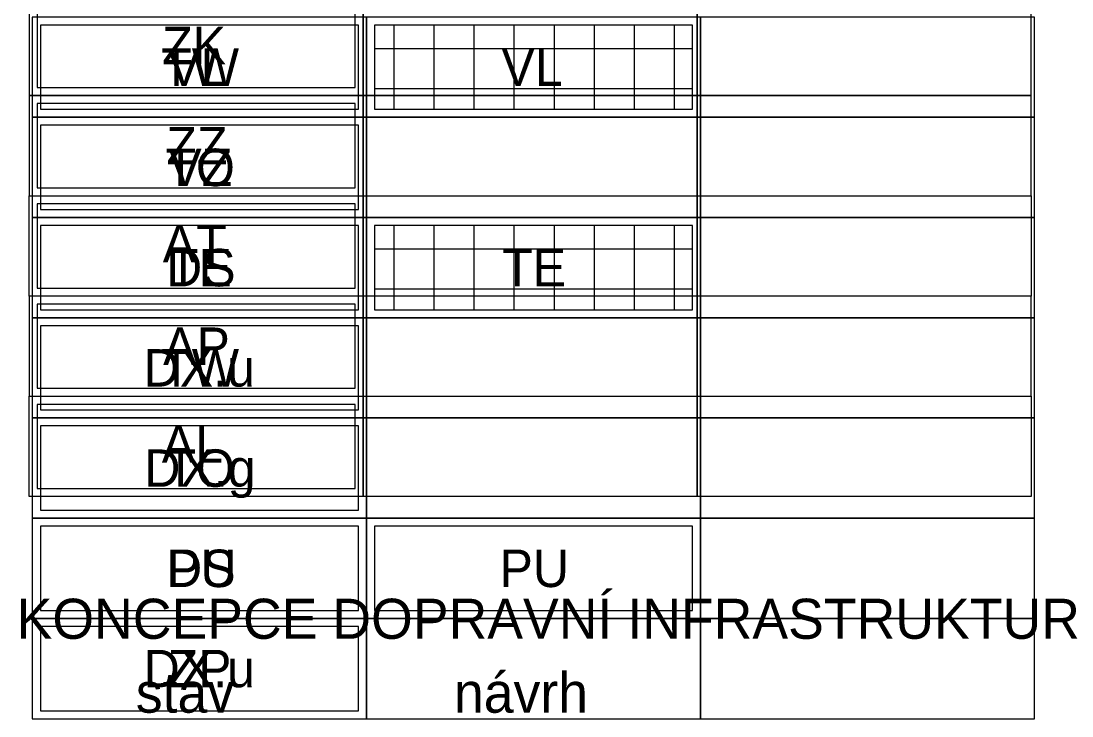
# Model space of a CAD drawing. Extents: x -557692 to -550384, y -1187532 to -1181973.
# Drawn here: x -552824 to -552430.7, y -1183626.2 to -1183366.2 of the extents above; entities that cross this region are included whole.
import ezdxf

# ---------------------------------------------------------------- set-up
doc = ezdxf.new("R2010")
doc.units = 0
for name, color, linetype in [('LEG_2a', 7, 'Continuous'), ('LEG_2b', 7, 'Continuous'), ('LEG_4_KOO', 7, 'Continuous')]:
    doc.layers.add(name, color=color, linetype=linetype)

msp = doc.modelspace()

# ---------------------------------------------------------------- linework, layer by layer
at = {"layer": 'LEG_2a'}
for points in [[(-552820.95, -1183394.08), (-552695.95, -1183394.08), (-552695.95, -1183356.58), (-552820.95, -1183356.58)], [(-552695.95, -1183394.08), (-552570.95, -1183394.08), (-552570.95, -1183356.58), (-552695.95, -1183356.58)], [(-552570.95, -1183394.08), (-552445.95, -1183394.08), (-552445.95, -1183356.58), (-552570.95, -1183356.58)], [(-552817.95, -1183391.08), (-552698.95, -1183391.08), (-552698.95, -1183359.58), (-552817.95, -1183359.58)], [(-552817.95, -1183391.08), (-552698.95, -1183391.08), (-552698.95, -1183359.58), (-552817.95, -1183359.58)], [(-552820.95, -1183431.58), (-552695.95, -1183431.58), (-552695.95, -1183394.08), (-552820.95, -1183394.08)], [(-552817.95, -1183428.58), (-552698.95, -1183428.58), (-552698.95, -1183397.08), (-552817.95, -1183397.08)], [(-552817.95, -1183428.58), (-552698.95, -1183428.58), (-552698.95, -1183397.08), (-552817.95, -1183397.08)], [(-552695.95, -1183431.58), (-552570.95, -1183431.58), (-552570.95, -1183394.08), (-552695.95, -1183394.08)], [(-552570.95, -1183431.58), (-552445.95, -1183431.58), (-552445.95, -1183394.08), (-552570.95, -1183394.08)], [(-552820.95, -1183431.58), (-552695.95, -1183431.58), (-552695.95, -1183469.08), (-552820.95, -1183469.08)], [(-552820.95, -1183431.58), (-552695.95, -1183431.58), (-552695.95, -1183469.08), (-552820.95, -1183469.08)], [(-552695.95, -1183431.58), (-552570.95, -1183431.58), (-552570.95, -1183469.08), (-552695.95, -1183469.08)], [(-552570.95, -1183431.58), (-552445.95, -1183431.58), (-552445.95, -1183469.08), (-552570.95, -1183469.08)], [(-552817.95, -1183466.08), (-552698.95, -1183466.08), (-552698.95, -1183434.58), (-552817.95, -1183434.58)], [(-552817.95, -1183466.08), (-552698.95, -1183466.08), (-552698.95, -1183434.58), (-552817.95, -1183434.58)], [(-552820.95, -1183506.58), (-552695.95, -1183506.58), (-552695.95, -1183469.08), (-552820.95, -1183469.08)], [(-552817.95, -1183503.58), (-552698.95, -1183503.58), (-552698.95, -1183472.08), (-552817.95, -1183472.08)], [(-552817.95, -1183503.58), (-552698.95, -1183503.58), (-552698.95, -1183472.08), (-552817.95, -1183472.08)], [(-552695.95, -1183506.58), (-552570.95, -1183506.58), (-552570.95, -1183469.08), (-552695.95, -1183469.08)], [(-552570.95, -1183506.58), (-552445.95, -1183506.58), (-552445.95, -1183469.08), (-552570.95, -1183469.08)], [(-552820.95, -1183506.58), (-552695.95, -1183506.58), (-552695.95, -1183544.08), (-552820.95, -1183544.08)], [(-552820.95, -1183506.58), (-552695.95, -1183506.58), (-552695.95, -1183544.08), (-552820.95, -1183544.08)], [(-552695.95, -1183506.58), (-552570.95, -1183506.58), (-552570.95, -1183544.08), (-552695.95, -1183544.08)], [(-552570.95, -1183506.58), (-552445.95, -1183506.58), (-552445.95, -1183544.08), (-552570.95, -1183544.08)], [(-552817.95, -1183541.08), (-552698.95, -1183541.08), (-552698.95, -1183509.58), (-552817.95, -1183509.58)], [(-552817.95, -1183541.08), (-552698.95, -1183541.08), (-552698.95, -1183509.58), (-552817.95, -1183509.58)]]:
    msp.add_lwpolyline(points, close=True, dxfattribs=at)
at = {"layer": 'LEG_2b'}
for points in [[(-552819.73, -1183402.18), (-552694.73, -1183402.18), (-552694.73, -1183364.68), (-552819.73, -1183364.68)], [(-552694.73, -1183402.18), (-552569.73, -1183402.18), (-552569.73, -1183364.68), (-552694.73, -1183364.68)], [(-552569.73, -1183402.18), (-552444.73, -1183402.18), (-552444.73, -1183364.68), (-552569.73, -1183364.68)], [(-552816.73, -1183399.18), (-552697.73, -1183399.18), (-552697.73, -1183367.68), (-552816.73, -1183367.68)], [(-552816.73, -1183399.18), (-552697.73, -1183399.18), (-552697.73, -1183367.68), (-552816.73, -1183367.68)], [(-552819.73, -1183439.68), (-552694.73, -1183439.68), (-552694.73, -1183402.18), (-552819.73, -1183402.18)], [(-552816.73, -1183436.68), (-552697.73, -1183436.68), (-552697.73, -1183405.18), (-552816.73, -1183405.18)], [(-552816.73, -1183436.68), (-552697.73, -1183436.68), (-552697.73, -1183405.18), (-552816.73, -1183405.18)], [(-552694.73, -1183439.68), (-552569.73, -1183439.68), (-552569.73, -1183402.18), (-552694.73, -1183402.18)], [(-552569.73, -1183439.68), (-552444.73, -1183439.68), (-552444.73, -1183402.18), (-552569.73, -1183402.18)], [(-552819.73, -1183477.18), (-552694.73, -1183477.18), (-552694.73, -1183439.68), (-552819.73, -1183439.68)], [(-552694.73, -1183477.18), (-552569.73, -1183477.18), (-552569.73, -1183439.68), (-552694.73, -1183439.68)], [(-552569.73, -1183477.18), (-552444.73, -1183477.18), (-552444.73, -1183439.68), (-552569.73, -1183439.68)], [(-552816.73, -1183474.18), (-552697.73, -1183474.18), (-552697.73, -1183442.68), (-552816.73, -1183442.68)], [(-552816.73, -1183474.18), (-552697.73, -1183474.18), (-552697.73, -1183442.68), (-552816.73, -1183442.68)], [(-552819.73, -1183514.68), (-552694.73, -1183514.68), (-552694.73, -1183477.18), (-552819.73, -1183477.18)], [(-552694.73, -1183514.68), (-552569.73, -1183514.68), (-552569.73, -1183477.18), (-552694.73, -1183477.18)], [(-552569.73, -1183514.68), (-552444.73, -1183514.68), (-552444.73, -1183477.18), (-552569.73, -1183477.18)], [(-552816.73, -1183511.68), (-552697.73, -1183511.68), (-552697.73, -1183480.18), (-552816.73, -1183480.18)], [(-552816.73, -1183511.68), (-552697.73, -1183511.68), (-552697.73, -1183480.18), (-552816.73, -1183480.18)], [(-552819.73, -1183552.18), (-552694.73, -1183552.18), (-552694.73, -1183514.68), (-552819.73, -1183514.68)], [(-552694.73, -1183552.18), (-552569.73, -1183552.18), (-552569.73, -1183514.68), (-552694.73, -1183514.68)], [(-552569.73, -1183552.18), (-552444.73, -1183552.18), (-552444.73, -1183514.68), (-552569.73, -1183514.68)], [(-552816.73, -1183549.18), (-552697.73, -1183549.18), (-552697.73, -1183517.68), (-552816.73, -1183517.68)], [(-552816.73, -1183549.18), (-552697.73, -1183549.18), (-552697.73, -1183517.68), (-552816.73, -1183517.68)], [(-552819.73, -1183589.68), (-552694.73, -1183589.68), (-552694.73, -1183552.18), (-552819.73, -1183552.18)], [(-552694.73, -1183589.68), (-552569.73, -1183589.68), (-552569.73, -1183552.18), (-552694.73, -1183552.18)], [(-552569.73, -1183589.68), (-552444.73, -1183589.68), (-552444.73, -1183552.18), (-552569.73, -1183552.18)], [(-552816.73, -1183586.68), (-552697.73, -1183586.68), (-552697.73, -1183555.18), (-552816.73, -1183555.18)], [(-552816.73, -1183586.68), (-552697.73, -1183586.68), (-552697.73, -1183555.18), (-552816.73, -1183555.18)], [(-552691.73, -1183586.68), (-552572.73, -1183586.68), (-552572.73, -1183555.18), (-552691.73, -1183555.18)], [(-552691.73, -1183586.68), (-552572.73, -1183586.68), (-552572.73, -1183555.18), (-552691.73, -1183555.18)], [(-552819.73, -1183627.18), (-552694.73, -1183627.18), (-552694.73, -1183589.68), (-552819.73, -1183589.68)], [(-552694.73, -1183627.18), (-552569.73, -1183627.18), (-552569.73, -1183589.68), (-552694.73, -1183589.68)], [(-552569.73, -1183627.18), (-552444.73, -1183627.18), (-552444.73, -1183589.68), (-552569.73, -1183589.68)], [(-552816.73, -1183624.18), (-552697.73, -1183624.18), (-552697.73, -1183592.68), (-552816.73, -1183592.68)], [(-552816.73, -1183624.18), (-552697.73, -1183624.18), (-552697.73, -1183592.68), (-552816.73, -1183592.68)]]:
    msp.add_lwpolyline(points, close=True, dxfattribs=at)
msp.add_lwpolyline([(-552691.73, -1183586.68), (-552572.73, -1183586.68), (-552572.73, -1183555.18), (-552691.73, -1183555.18), (-552691.73, -1183586.68)], dxfattribs=at)
at = {"layer": 'LEG_4_KOO'}
for p, q in [((-552684.4, -1183399.18), (-552684.4, -1183367.68)), ((-552669.4, -1183399.18), (-552669.4, -1183367.68)), ((-552654.4, -1183399.18), (-552654.4, -1183367.68)), ((-552639.4, -1183399.18), (-552639.4, -1183367.68)), ((-552624.4, -1183399.18), (-552624.4, -1183367.68)), ((-552609.4, -1183399.18), (-552609.4, -1183367.68)), ((-552594.4, -1183399.18), (-552594.4, -1183367.68)), ((-552579.4, -1183399.18), (-552579.4, -1183367.68)), ((-552691.73, -1183376.42), (-552572.73, -1183376.42)), ((-552691.73, -1183391.42), (-552572.73, -1183391.42)), ((-552684.4, -1183474.18), (-552684.4, -1183442.68)), ((-552669.4, -1183474.18), (-552669.4, -1183442.68)), ((-552654.4, -1183474.18), (-552654.4, -1183442.68)), ((-552639.4, -1183474.18), (-552639.4, -1183442.68)), ((-552624.4, -1183474.18), (-552624.4, -1183442.68)), ((-552609.4, -1183474.18), (-552609.4, -1183442.68)), ((-552594.4, -1183474.18), (-552594.4, -1183442.68)), ((-552579.4, -1183474.18), (-552579.4, -1183442.68)), ((-552691.73, -1183451.42), (-552572.73, -1183451.42)), ((-552691.73, -1183466.42), (-552572.73, -1183466.42))]:
    msp.add_line(p, q, dxfattribs=at)
for points in [[(-552819.73, -1183402.18), (-552694.73, -1183402.18), (-552694.73, -1183364.68), (-552819.73, -1183364.68)], [(-552694.73, -1183402.18), (-552569.73, -1183402.18), (-552569.73, -1183364.68), (-552694.73, -1183364.68)], [(-552569.73, -1183402.18), (-552444.73, -1183402.18), (-552444.73, -1183364.68), (-552569.73, -1183364.68)], [(-552816.73, -1183399.18), (-552697.73, -1183399.18), (-552697.73, -1183367.68), (-552816.73, -1183367.68)], [(-552816.73, -1183399.18), (-552697.73, -1183399.18), (-552697.73, -1183367.68), (-552816.73, -1183367.68)], [(-552691.73, -1183399.18), (-552572.73, -1183399.18), (-552572.73, -1183367.68), (-552691.73, -1183367.68)], [(-552691.73, -1183399.18), (-552572.73, -1183399.18), (-552572.73, -1183367.68), (-552691.73, -1183367.68)], [(-552819.73, -1183439.68), (-552694.73, -1183439.68), (-552694.73, -1183402.18), (-552819.73, -1183402.18)], [(-552816.73, -1183436.68), (-552697.73, -1183436.68), (-552697.73, -1183405.18), (-552816.73, -1183405.18)], [(-552816.73, -1183436.68), (-552697.73, -1183436.68), (-552697.73, -1183405.18), (-552816.73, -1183405.18)], [(-552694.73, -1183439.68), (-552569.73, -1183439.68), (-552569.73, -1183402.18), (-552694.73, -1183402.18)], [(-552569.73, -1183439.68), (-552444.73, -1183439.68), (-552444.73, -1183402.18), (-552569.73, -1183402.18)], [(-552819.73, -1183477.18), (-552694.73, -1183477.18), (-552694.73, -1183439.68), (-552819.73, -1183439.68)], [(-552694.73, -1183477.18), (-552569.73, -1183477.18), (-552569.73, -1183439.68), (-552694.73, -1183439.68)], [(-552569.73, -1183477.18), (-552444.73, -1183477.18), (-552444.73, -1183439.68), (-552569.73, -1183439.68)], [(-552816.73, -1183474.18), (-552697.73, -1183474.18), (-552697.73, -1183442.68), (-552816.73, -1183442.68)], [(-552816.73, -1183474.18), (-552697.73, -1183474.18), (-552697.73, -1183442.68), (-552816.73, -1183442.68)], [(-552691.73, -1183474.18), (-552572.73, -1183474.18), (-552572.73, -1183442.68), (-552691.73, -1183442.68)], [(-552691.73, -1183474.18), (-552572.73, -1183474.18), (-552572.73, -1183442.68), (-552691.73, -1183442.68)], [(-552819.73, -1183514.68), (-552694.73, -1183514.68), (-552694.73, -1183477.18), (-552819.73, -1183477.18)], [(-552694.73, -1183514.68), (-552569.73, -1183514.68), (-552569.73, -1183477.18), (-552694.73, -1183477.18)], [(-552569.73, -1183514.68), (-552444.73, -1183514.68), (-552444.73, -1183477.18), (-552569.73, -1183477.18)], [(-552816.73, -1183511.68), (-552697.73, -1183511.68), (-552697.73, -1183480.18), (-552816.73, -1183480.18)], [(-552816.73, -1183511.68), (-552697.73, -1183511.68), (-552697.73, -1183480.18), (-552816.73, -1183480.18)], [(-552819.73, -1183552.18), (-552694.73, -1183552.18), (-552694.73, -1183514.68), (-552819.73, -1183514.68)], [(-552694.73, -1183552.18), (-552569.73, -1183552.18), (-552569.73, -1183514.68), (-552694.73, -1183514.68)], [(-552569.73, -1183552.18), (-552444.73, -1183552.18), (-552444.73, -1183514.68), (-552569.73, -1183514.68)], [(-552816.73, -1183549.18), (-552697.73, -1183549.18), (-552697.73, -1183517.68), (-552816.73, -1183517.68)], [(-552816.73, -1183549.18), (-552697.73, -1183549.18), (-552697.73, -1183517.68), (-552816.73, -1183517.68)], [(-552819.73, -1183589.68), (-552694.73, -1183589.68), (-552694.73, -1183552.18), (-552819.73, -1183552.18)], [(-552694.73, -1183589.68), (-552569.73, -1183589.68), (-552569.73, -1183552.18), (-552694.73, -1183552.18)], [(-552569.73, -1183589.68), (-552444.73, -1183589.68), (-552444.73, -1183552.18), (-552569.73, -1183552.18)], [(-552816.73, -1183586.68), (-552697.73, -1183586.68), (-552697.73, -1183555.18), (-552816.73, -1183555.18)], [(-552816.73, -1183586.68), (-552697.73, -1183586.68), (-552697.73, -1183555.18), (-552816.73, -1183555.18)], [(-552819.73, -1183627.18), (-552694.73, -1183627.18), (-552694.73, -1183589.68), (-552819.73, -1183589.68)], [(-552694.73, -1183627.18), (-552569.73, -1183627.18), (-552569.73, -1183589.68), (-552694.73, -1183589.68)], [(-552569.73, -1183627.18), (-552444.73, -1183627.18), (-552444.73, -1183589.68), (-552569.73, -1183589.68)], [(-552816.73, -1183624.18), (-552697.73, -1183624.18), (-552697.73, -1183592.68), (-552816.73, -1183592.68)], [(-552816.73, -1183624.18), (-552697.73, -1183624.18), (-552697.73, -1183592.68), (-552816.73, -1183592.68)]]:
    msp.add_lwpolyline(points, close=True, dxfattribs=at)

# ---------------------------------------------------------------- texts
at = {"layer": 'LEG_2a'}
for s, height, p in [('ZK', 14, (-552771.2, -1183382.33)), ('ZZ', 14, (-552769.61, -1183419.83)), ('AT', 14, (-552770.92, -1183456.44)), ('AP', 14, (-552770.79, -1183494.83)), ('AL', 14, (-552771.3, -1183531.44)), ('KONCEPCE DOPRAVNÍ INFRASTRUKTURY', 15, (-552825.61, -1183597.3)), ('návrh', 15, (-552661.98, -1183624.94)), ('stav', 15, (-552781.01, -1183624.94))]:
    msp.add_text(s, height=height, dxfattribs=at).set_placement(p)
at = {"layer": 'LEG_2b'}
for s, p in [('TW', (-552771.5, -1183390.43)), ('TO', (-552769.92, -1183427.93)), ('DS', (-552769.67, -1183465.43)), ('DX.u', (-552778.07, -1183502.93)), ('DX.g', (-552777.82, -1183540.43)), ('PU', (-552769.33, -1183577.93)), ('PU', (-552644.92, -1183577.93)), ('ZP', (-552769.15, -1183615.43))]:
    msp.add_text(s, height=14, dxfattribs=at).set_placement(p)
at = {"layer": 'LEG_4_KOO'}
for s, p in [('VL', (-552769.21, -1183390.43)), ('VL', (-552644.21, -1183390.43)), ('VZ', (-552768.83, -1183427.93)), ('TE', (-552768.96, -1183465.43)), ('TE', (-552643.96, -1183465.43)), ('TW', (-552771.5, -1183502.93)), ('TO', (-552769.92, -1183540.43)), ('DS', (-552769.67, -1183577.93)), ('DX.u', (-552778.07, -1183615.43))]:
    msp.add_text(s, height=14, dxfattribs=at).set_placement(p)

doc.saveas('drawing.dxf')
